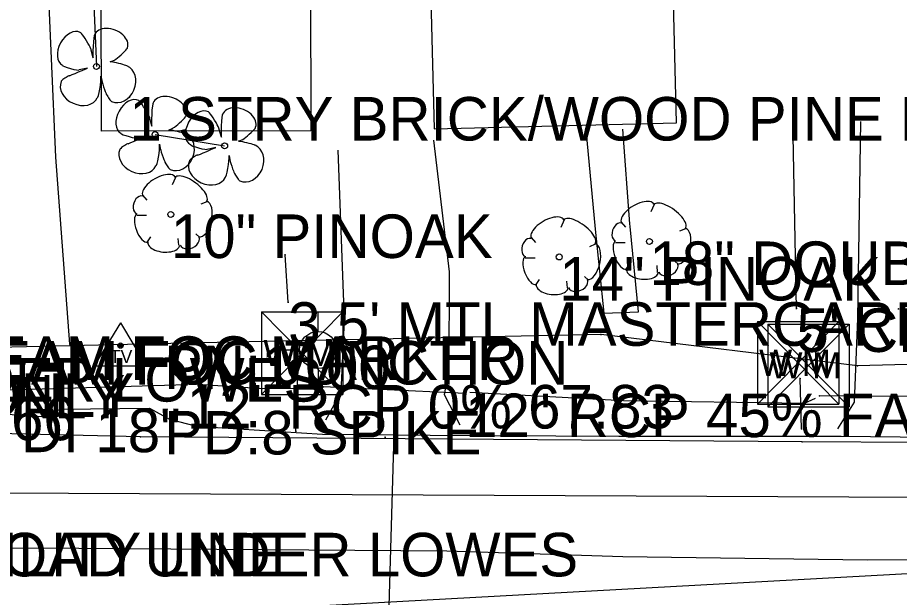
# Model space of a CAD drawing. Extents: x 1304270 to 1306561, y 1876019 to 1876752.
# Drawn here: x 1305034.9 to 1305136, y 1876403.7 to 1876470.3 of the extents above; entities that cross this region are included whole.
import ezdxf

# ---------------------------------------------------------------- set-up
doc = ezdxf.new("R2010")
doc.units = 0
for name, color, linetype in [('Default', 7, 'Continuous'), ('S_BUILDING', 7, 'Continuous'), ('S_BUILDING_ANNOT', 7, 'Continuous'), ('S_DITCHLINE', 7, 'Continuous'), ('S_DRG_PT_SYM', 7, 'Continuous'), ('S_DRIVEWAY', 7, 'Continuous'), ('S_EDGE_PAVEMENT', 7, 'Continuous'), ('S_ELECTRIC_UTILITIES_ANNOT', 7, 'Continuous'), ('S_FENCE', 7, 'Continuous'), ('S_FENCE_ANNOT', 7, 'Continuous'), ('S_FIBER_OPTIC_CABLE', 7, 'Continuous'), ('S_MSC_PT_SYM', 7, 'Continuous'), ('S_PAVEMENT_CROWN', 7, 'Continuous'), ('S_SANITARY_SEWER', 7, 'Continuous'), ('S_SECONDARY_CTL', 7, 'Continuous'), ('S_SECONDARY_CTL_ANNOT', 7, 'Continuous'), ('S_SIDE_DRAIN', 7, 'Continuous'), ('S_SIDE_DRAIN_ANNOT', 7, 'Continuous'), ('S_SIDEWALK', 7, 'Continuous'), ('S_SIGN', 7, 'Continuous'), ('S_SIGN_ANNOT', 7, 'Continuous'), ('S_STORM_SEWER_ANNOT', 7, 'Continuous'), ('S_STR_PT_SYM', 7, 'Continuous'), ('S_SURVEY_TEXT_ANNOT', 7, 'Continuous'), ('S_TELEPHONE_UTILITIES_ANNOT', 7, 'Continuous'), ('S_TREE', 7, 'Continuous'), ('S_TREE_ANNOT', 7, 'Continuous'), ('S_UTILITY_POLE', 7, 'Continuous'), ('S_UTILITY_POLE_ANNOT', 7, 'Continuous'), ('S_UTL_PT_SYM', 7, 'Continuous'), ('S_WATER_UTILITIES', 7, 'Continuous')]:
    doc.layers.add(name, color=color, linetype=linetype)

msp = doc.modelspace()

# ---------------------------------------------------------------- linework, layer by layer
at = {"layer": 'Default'}
msp.add_line((1304873.94, 1876392.06), (1305473.53, 1876424.94), dxfattribs=at)
at = {"layer": 'S_BUILDING'}
for points in [[(1305044.48, 1876457.27), (1305044.38, 1876507.06), (1305040.43, 1876507.05), (1305040.41, 1876515.92), (1305043.37, 1876515.92), (1305043.27, 1876566.2), (1305064.01, 1876566.25), (1305064.12, 1876507.43), (1305068.4, 1876507.44), (1305068.5, 1876457.32)], [(1305110.49, 1876458.23), (1305109.44, 1876499.79), (1305081.6, 1876499.08), (1305082.65, 1876457.52)]]:
    msp.add_lwpolyline(points, close=True, dxfattribs=at)
at = {"layer": 'S_DITCHLINE'}
for points in [[(1305054.97, 1876428.26), (1305062.99, 1876427.7), (1305069.3, 1876427.77)], [(1305086.77, 1876427.29), (1305104.4, 1876426.33), (1305125.17, 1876426.04), (1305126.42, 1876426.61)]]:
    msp.add_lwpolyline(points, dxfattribs=at)
at = {"layer": 'S_DRG_PT_SYM'}
for points in [[(1305054.28, 1876428.12), (1305054.28, 1876428.17), (1305054.28, 1876428.12), (1305054.23, 1876428.12), (1305054.28, 1876428.12), (1305054.28, 1876428.07), (1305054.28, 1876428.12), (1305054.33, 1876428.12)], [(1305069.97, 1876427.91), (1305069.97, 1876427.96), (1305069.97, 1876427.91), (1305069.92, 1876427.91), (1305069.97, 1876427.91), (1305069.97, 1876427.86), (1305069.97, 1876427.91), (1305070.02, 1876427.91)], [(1305086.22, 1876427.13), (1305086.22, 1876427.18), (1305086.22, 1876427.13), (1305086.17, 1876427.13), (1305086.22, 1876427.13), (1305086.22, 1876427.08), (1305086.22, 1876427.13), (1305086.27, 1876427.13)], [(1305126.89, 1876426.87), (1305126.89, 1876426.92), (1305126.89, 1876426.87), (1305126.84, 1876426.87), (1305126.89, 1876426.87), (1305126.89, 1876426.82), (1305126.89, 1876426.87), (1305126.94, 1876426.87)]]:
    msp.add_lwpolyline(points, dxfattribs=at)
at = {"layer": 'S_DRIVEWAY'}
for points in [[(1305045.18, 1876426.29), (1305040.87, 1876432.82), (1305039.24, 1876454.28), (1305038.25, 1876476.97), (1305037.26, 1876499.66)], [(1305129, 1876423.09), (1305130.9, 1876426.13), (1305131.29, 1876435.75), (1305131.62, 1876458.39)], [(1305082.58, 1876456.23), (1305084.4, 1876441.12), (1305084.34, 1876429.84), (1305083.83, 1876427.04), (1305085.6, 1876423.53)], [(1305070.25, 1876424.11), (1305071.99, 1876427.31), (1305072.37, 1876435.56), (1305071.64, 1876455.07)]]:
    msp.add_lwpolyline(points, dxfattribs=at)
at = {"layer": 'S_EDGE_PAVEMENT'}
msp.add_lwpolyline([(1305027.35, 1876425.19), (1305037.63, 1876424.5), (1305039.84, 1876425.35), (1305050, 1876425.46), (1305052.3, 1876424.19), (1305055.39, 1876423.4), (1305069.86, 1876422.47), (1305082.2, 1876422.36), (1305103.86, 1876422.24), (1305116.61, 1876422.24), (1305129.36, 1876422.24), (1305153.05, 1876421.96)], dxfattribs=at)
at = {"layer": 'S_FENCE'}
msp.add_line((1305124.23, 1876436.91), (1305123.87, 1876456.74), dxfattribs=at)
msp.add_lwpolyline([(1305124.23, 1876436.91), (1305123.87, 1876456.74)], dxfattribs=at)
msp.add_lwpolyline([(1305124.23, 1876436.91), (1305123.87, 1876456.74)], dxfattribs=at)
at = {"layer": 'S_FIBER_OPTIC_CABLE'}
for p, q in [((1305101.81, 1876433.92), (1305054.08, 1876432.91)), ((1305131.24, 1876430.32), (1305101.81, 1876433.92)), ((1305054.08, 1876432.91), (1305001.63, 1876431.73)), ((1305161.12, 1876431.11), (1305131.24, 1876430.32))]:
    msp.add_line(p, q, dxfattribs=at)
at = {"layer": 'S_MSC_PT_SYM'}
for points in [[(1305123.87, 1876456.74), (1305123.87, 1876456.79), (1305123.87, 1876456.74), (1305123.82, 1876456.74), (1305123.87, 1876456.74), (1305123.87, 1876456.69), (1305123.87, 1876456.74), (1305123.92, 1876456.74)], [(1305065.55, 1876443.07), (1305065.55, 1876443.12), (1305065.55, 1876443.07), (1305065.5, 1876443.07), (1305065.55, 1876443.07), (1305065.55, 1876443.02), (1305065.55, 1876443.07), (1305065.6, 1876443.07)], [(1305065.91, 1876437.62), (1305065.91, 1876437.67), (1305065.91, 1876437.62), (1305065.86, 1876437.62), (1305065.91, 1876437.62), (1305065.91, 1876437.57), (1305065.91, 1876437.62), (1305065.96, 1876437.62)], [(1305124.23, 1876436.91), (1305124.23, 1876436.96), (1305124.23, 1876436.91), (1305124.18, 1876436.91), (1305124.23, 1876436.91), (1305124.23, 1876436.86), (1305124.23, 1876436.91), (1305124.28, 1876436.91)], [(1305135.95, 1876436.85), (1305135.95, 1876436.9), (1305135.95, 1876436.85), (1305135.9, 1876436.85), (1305135.95, 1876436.85), (1305135.95, 1876436.8), (1305135.95, 1876436.85), (1305136, 1876436.85)]]:
    msp.add_lwpolyline(points, dxfattribs=at)
at = {"layer": 'S_PAVEMENT_CROWN'}
msp.add_lwpolyline([(1304919.66, 1876411.01), (1304932.57, 1876410.53), (1304945.47, 1876410.05), (1304958.3, 1876409.86), (1304971.12, 1876409.67), (1304984.31, 1876409.56), (1304997.49, 1876409.46), (1305019.68, 1876409.41), (1305041.87, 1876409.36), (1305062.99, 1876409.23), (1305084.1, 1876409.09), (1305104.33, 1876408.42), (1305118.33, 1876408.24), (1305132.34, 1876408.05), (1305154.42, 1876408.07)], dxfattribs=at)
at = {"layer": 'S_SANITARY_SEWER'}
msp.add_line((1304983.66, 1876415.96), (1305346.23, 1876414.24), dxfattribs=at)
at = {"layer": 'S_SECONDARY_CTL'}
for p, q in [((1305046.67, 1876435.25), (1305043.66, 1876430.3)), ((1305046.67, 1876435.25), (1305049.62, 1876430.3)), ((1305043.66, 1876430.3), (1305049.62, 1876430.3))]:
    msp.add_line(p, q, dxfattribs=at)
for radius in [0.311, 0.183, 0.103]:
    msp.add_circle((1305046.67, 1876432.64), radius, dxfattribs=at)
at = {"layer": 'S_SIDE_DRAIN'}
for p, q in [((1305054.28, 1876428.12), (1304986.49, 1876426.16)), ((1305086.22, 1876427.13), (1305069.97, 1876427.91)), ((1305143.1, 1876426.78), (1305126.89, 1876426.87))]:
    msp.add_line(p, q, dxfattribs=at)
at = {"layer": 'S_SIDEWALK'}
msp.add_lwpolyline([(1305100.06, 1876457.44), (1305101.13, 1876446.01), (1305102.12, 1876436.36), (1305106.12, 1876436.52), (1305105.17, 1876446.32), (1305105.1, 1876446.62), (1305104.32, 1876457.49)], dxfattribs=at)
at = {"layer": 'S_SIGN'}
msp.add_line((1305065.91, 1876437.62), (1305065.55, 1876443.07), dxfattribs=at)
at = {"layer": 'S_STR_PT_SYM'}
msp.add_lwpolyline([(1305047.7, 1876461.19), (1305047.7, 1876461.24), (1305047.7, 1876461.19), (1305047.65, 1876461.19), (1305047.7, 1876461.19), (1305047.7, 1876461.14), (1305047.7, 1876461.19), (1305047.75, 1876461.19)], dxfattribs=at)
at = {"layer": 'S_TREE'}
for p, q in [((1305042.39, 1876501.21), (1305043.91, 1876464.7)), ((1305043.55, 1876465.68), (1305043.3, 1876466.57)), ((1305045.49, 1876465.22), (1305045.87, 1876465.38)), ((1305042.9, 1876464.51), (1305041.92, 1876464.3)), ((1305044.43, 1876463.58), (1305044.51, 1876463.14)), ((1305050.27, 1876457.86), (1305050.03, 1876458.76)), ((1305052.22, 1876457.4), (1305052.6, 1876457.56)), ((1305058.25, 1876456.56), (1305058.01, 1876457.45)), ((1305049.62, 1876456.7), (1305048.65, 1876456.48)), ((1305050.64, 1876456.88), (1305058.62, 1876455.58)), ((1305060.2, 1876456.1), (1305060.58, 1876456.26)), ((1305051.15, 1876455.77), (1305051.23, 1876455.33)), ((1305057.6, 1876455.4), (1305056.63, 1876455.18)), ((1305059.14, 1876454.47), (1305059.22, 1876454.03)), ((1305052.99, 1876451.95), (1305052.61, 1876451.1)), ((1305049.2, 1876449.93), (1305049.7, 1876449.35)), ((1305056.56, 1876449.16), (1305055.9, 1876448.89)), ((1305107.93, 1876448.84), (1305107.54, 1876447.99)), ((1305048.54, 1876447.61), (1305049.66, 1876447.61)), ((1305097.57, 1876447.07), (1305097.19, 1876446.21)), ((1305104.13, 1876446.83), (1305104.63, 1876446.25)), ((1305111.49, 1876446.05), (1305110.83, 1876445.78)), ((1305049.7, 1876444.43), (1305050.16, 1876445.13)), ((1305053.38, 1876444.16), (1305053.3, 1876444.94)), ((1305055.78, 1876445.05), (1305055.32, 1876445.48)), ((1305093.78, 1876445.05), (1305094.28, 1876444.47)), ((1305101.14, 1876444.28), (1305100.48, 1876444)), ((1305103.47, 1876444.5), (1305104.59, 1876444.5)), ((1305093.12, 1876442.73), (1305094.24, 1876442.73)), ((1305104.63, 1876441.32), (1305105.1, 1876442.02)), ((1305108.31, 1876441.05), (1305108.24, 1876441.83)), ((1305110.72, 1876441.94), (1305110.25, 1876442.37)), ((1305094.28, 1876439.55), (1305094.74, 1876440.25)), ((1305097.96, 1876439.28), (1305097.88, 1876440.05)), ((1305100.36, 1876440.17), (1305099.9, 1876440.59))]:
    msp.add_line(p, q, dxfattribs=at)
for centre in [(1305043.91, 1876464.7), (1305050.64, 1876456.88), (1305058.62, 1876455.58), (1305052.44, 1876447.7), (1305107.37, 1876444.6), (1305097.02, 1876442.82)]:
    msp.add_circle(centre, 0.341, dxfattribs=at)
for centre, major_axis, ratio, start_param, end_param in [((1305045.57, 1876467.59), (1.89, -0.74), 0.673998, 0, 3.141593), ((1305041.03, 1876466.72), (-1.03, -1.88), 0.662338, 3.141593, 6.283185), ((1305042.68, 1876467.59), (0.62, -1.01), 0.083512, 0, 3.141593), ((1305043.61, 1876467), (-0.07, -1.33), 0.068203, 3.141593, 6.283185), ((1305046.67, 1876466.11), (-0.798, -0.73), 0.092159, 0, 3.141593), ((1305046.45, 1876464.99), (0.96, -0.23), 0.056001, 0, 3.141593), ((1305040.96, 1876464.57), (0.964, -0.267), 0.113563, 3.141593, 6.283185), ((1305041.86, 1876464.07), (1.04, 0.44), 0.002756, 3.141593, 6.283185), ((1305046.53, 1876462.71), (0.88, 2.05), 0.81717, 3.141593, 6.283185), ((1305041.94, 1876462.04), (2.07, -0.93), 0.760068, 3.141593, 6.283185), ((1305040.34, 1876463.3), (0.477, 0.328), 0.136309, 0, 3.141593), ((1305044.19, 1876462.42), (0.19, 1.31), 0.114148, 3.141593, 5.822668), ((1305044.76, 1876462.37), (0.254, -0.771), 0.051603, 3.141593, 6.283185), ((1305045.34, 1876461.14), (-0.321, 0.467), 0.094289, 0, 3.141593), ((1305047.75, 1876458.9), (-1.03, -1.88), 0.662338, 3.141593, 6.283185), ((1305052.3, 1876459.77), (1.89, -0.74), 0.673998, 0, 3.141593), ((1305049.4, 1876459.77), (0.62, -1.01), 0.083512, 0, 3.141593), ((1305050.34, 1876459.19), (-0.07, -1.33), 0.068203, 3.141593, 6.283185), ((1305060.28, 1876458.47), (1.89, -0.74), 0.673998, 0, 3.141593), ((1305053.39, 1876458.3), (-0.798, -0.73), 0.092159, 0, 3.141593), ((1305055.73, 1876457.6), (-1.03, -1.88), 0.662338, 3.141593, 6.283185), ((1305057.39, 1876458.47), (0.62, -1.01), 0.083512, 0, 3.141593), ((1305058.32, 1876457.89), (-0.07, -1.33), 0.068203, 3.141593, 6.283185), ((1305047.68, 1876456.75), (0.964, -0.267), 0.113563, 3.141593, 6.283185), ((1305053.18, 1876457.17), (0.96, -0.23), 0.056001, 0, 3.141593), ((1305053.26, 1876454.9), (0.88, 2.05), 0.81717, 3.141593, 6.283185), ((1305061.38, 1876456.99), (-0.798, -0.73), 0.092159, 0, 3.141593), ((1305048.58, 1876456.26), (1.04, 0.44), 0.002756, 3.141593, 6.283185), ((1305061.16, 1876455.87), (0.96, -0.23), 0.056001, 0, 3.141593), ((1305048.66, 1876454.22), (2.07, -0.93), 0.760068, 3.141593, 6.283185), ((1305047.07, 1876455.48), (0.477, 0.328), 0.136309, 0, 3.141593), ((1305050.92, 1876454.6), (0.19, 1.31), 0.114148, 3.141593, 5.822668), ((1305051.49, 1876454.56), (0.254, -0.771), 0.051603, 3.141593, 6.283185), ((1305055.67, 1876455.45), (0.964, -0.267), 0.113563, 3.141593, 6.283185), ((1305056.57, 1876454.95), (1.04, 0.44), 0.002756, 3.141593, 6.283185), ((1305061.24, 1876453.6), (0.88, 2.05), 0.81717, 3.141593, 6.283185), ((1305055.05, 1876454.18), (0.477, 0.328), 0.136309, 0, 3.141593), ((1305058.9, 1876453.3), (0.19, 1.31), 0.114148, 3.141593, 5.822668), ((1305059.47, 1876453.26), (0.254, -0.771), 0.051603, 3.141593, 6.283185), ((1305052.06, 1876453.32), (-0.321, 0.467), 0.094289, 0, 3.141593), ((1305056.64, 1876452.92), (2.07, -0.93), 0.760068, 3.141593, 6.283185), ((1305051.1, 1876450.91), (1.86, 1.08), 0.471018, 0, 3.141593), ((1305054.75, 1876450.58), (-1.81, 1.36), 0.405113, 3.141593, 6.283186), ((1305060.05, 1876452.02), (-0.321, 0.467), 0.094289, 0, 3.141593), ((1305048.86, 1876448.79), (0.31, 1.03), 0.646762, 0, 3.141593), ((1305056.11, 1876447.17), (0.46, 2.04), 0.482994, 3.141593, 6.283185), ((1305106.03, 1876447.8), (1.86, 1.08), 0.471018, 0, 3.141593), ((1305109.69, 1876447.47), (-1.81, 1.36), 0.405113, 3.141593, 6.283186), ((1305049.17, 1876446.14), (-0.61, 1.6), 0.420543, 6.283185, 9.424777), ((1305095.68, 1876446.02), (1.86, 1.08), 0.471018, 0, 3.141593), ((1305099.33, 1876445.7), (-1.81, 1.36), 0.405113, 3.141593, 6.283186), ((1305103.8, 1876445.68), (0.31, 1.03), 0.646762, 0, 3.141593), ((1305111.04, 1876444.07), (0.46, 2.04), 0.482994, 3.141593, 6.283185), ((1305054.59, 1876444.65), (1.09, 0.46), 0.711534, 3.141592, 6.283185), ((1305093.44, 1876443.91), (0.31, 1.03), 0.646762, 0, 3.141593), ((1305051.63, 1876444.36), (-1.83, 0.19), 0.529943, 0, 3.141593), ((1305100.69, 1876442.29), (0.46, 2.04), 0.482994, 3.141593, 6.283185), ((1305104.1, 1876443.03), (-0.61, 1.6), 0.420543, 6.283185, 9.424777), ((1305093.75, 1876441.26), (-0.61, 1.6), 0.420543, 6.283185, 9.424777), ((1305109.52, 1876441.55), (1.09, 0.46), 0.711534, 3.141592, 6.283185), ((1305106.56, 1876441.25), (-1.83, 0.19), 0.529943, 0, 3.141593), ((1305099.17, 1876439.77), (1.09, 0.46), 0.711534, 3.141592, 6.283185), ((1305096.21, 1876439.48), (-1.83, 0.19), 0.529943, 0, 3.141593)]:
    msp.add_ellipse(centre, major_axis=major_axis, ratio=ratio, start_param=start_param, end_param=end_param, dxfattribs=at)
at = {"layer": 'S_UTILITY_POLE'}
for p, q in [((1305069.34, 1876434.24), (1305069.34, 1876436.49)), ((1305067.24, 1876432.11), (1305064.92, 1876432.11)), ((1305069.41, 1876427.69), (1305069.41, 1876430.02))]:
    msp.add_line(p, q, dxfattribs=at)
msp.add_circle((1305069.34, 1876432.13), 2.13, dxfattribs=at)
at = {"layer": 'S_UTL_PT_SYM'}
for points in [[(1305101.81, 1876433.92), (1305101.81, 1876433.97), (1305101.81, 1876433.92), (1305101.76, 1876433.92), (1305101.81, 1876433.92), (1305101.81, 1876433.87), (1305101.81, 1876433.92), (1305101.86, 1876433.92)], [(1305054.08, 1876432.91), (1305054.08, 1876432.96), (1305054.08, 1876432.91), (1305054.03, 1876432.91), (1305054.08, 1876432.91), (1305054.08, 1876432.86), (1305054.08, 1876432.91), (1305054.13, 1876432.91)], [(1305067.01, 1876429.81), (1305067.01, 1876429.86), (1305067.01, 1876429.81), (1305066.96, 1876429.81), (1305067.01, 1876429.81), (1305067.01, 1876429.76), (1305067.01, 1876429.81), (1305067.06, 1876429.81)], [(1305131.24, 1876430.32), (1305131.24, 1876430.37), (1305131.24, 1876430.32), (1305131.19, 1876430.32), (1305131.24, 1876430.32), (1305131.24, 1876430.27), (1305131.24, 1876430.32), (1305131.29, 1876430.32)], [(1305124.65, 1876428.86), (1305124.65, 1876428.91), (1305124.65, 1876428.86), (1305124.6, 1876428.86), (1305124.65, 1876428.86), (1305124.65, 1876428.81), (1305124.65, 1876428.86), (1305124.7, 1876428.86)], [(1305066.8, 1876422.81), (1305066.8, 1876422.86), (1305066.8, 1876422.81), (1305066.75, 1876422.81), (1305066.8, 1876422.81), (1305066.8, 1876422.76), (1305066.8, 1876422.81), (1305066.85, 1876422.81)], [(1305124.83, 1876423.08), (1305124.83, 1876423.13), (1305124.83, 1876423.08), (1305124.78, 1876423.08), (1305124.83, 1876423.08), (1305124.83, 1876423.03), (1305124.83, 1876423.08), (1305124.88, 1876423.08)], [(1305048.97, 1876422.17), (1305048.97, 1876422.22), (1305048.97, 1876422.17), (1305048.92, 1876422.17), (1305048.97, 1876422.17), (1305048.97, 1876422.12), (1305048.97, 1876422.17), (1305049.02, 1876422.17)], [(1305077.06, 1876422.11), (1305077.06, 1876422.16), (1305077.06, 1876422.11), (1305077.01, 1876422.11), (1305077.06, 1876422.11), (1305077.06, 1876422.06), (1305077.06, 1876422.11), (1305077.11, 1876422.11)], [(1305124.9, 1876421.59), (1305124.9, 1876421.64), (1305124.9, 1876421.59), (1305124.85, 1876421.59), (1305124.9, 1876421.59), (1305124.9, 1876421.54), (1305124.9, 1876421.59), (1305124.95, 1876421.59)], [(1305078.04, 1876421.15), (1305078.04, 1876421.2), (1305078.04, 1876421.15), (1305077.99, 1876421.15), (1305078.04, 1876421.15), (1305078.04, 1876421.1), (1305078.04, 1876421.15), (1305078.09, 1876421.15)]]:
    msp.add_lwpolyline(points, dxfattribs=at)
at = {"layer": 'S_WATER_UTILITIES'}
for p, q in [((1305062.86, 1876436.51), (1305072.2, 1876436.51)), ((1305062.86, 1876436.51), (1305062.86, 1876427.02)), ((1305062.86, 1876436.51), (1305072.2, 1876427.02)), ((1305072.2, 1876436.51), (1305062.86, 1876427.02)), ((1305072.2, 1876436.51), (1305072.2, 1876427.02)), ((1305119.75, 1876435.39), (1305129.09, 1876435.39)), ((1305119.75, 1876435.39), (1305119.75, 1876425.9)), ((1305119.75, 1876435.39), (1305129.09, 1876425.9)), ((1305129.09, 1876435.39), (1305119.75, 1876425.9)), ((1305120.95, 1876435.11), (1305130.29, 1876435.11)), ((1305120.95, 1876435.11), (1305120.95, 1876425.61)), ((1305120.95, 1876435.11), (1305130.29, 1876425.61)), ((1305130.29, 1876435.11), (1305120.95, 1876425.61)), ((1305129.09, 1876435.39), (1305129.09, 1876425.9)), ((1305130.29, 1876435.11), (1305130.29, 1876425.61)), ((1305066.8, 1876422.81), (1305067.01, 1876429.81)), ((1305124.83, 1876423.08), (1305124.65, 1876428.86)), ((1305062.86, 1876427.02), (1305072.2, 1876427.02)), ((1305119.75, 1876425.9), (1305129.09, 1876425.9)), ((1305120.95, 1876425.61), (1305130.29, 1876425.61)), ((1305048.97, 1876422.17), (1304991.8, 1876423.43)), ((1305124.9, 1876421.59), (1305048.97, 1876422.17)), ((1305219.44, 1876420.93), (1305124.9, 1876421.59)), ((1305077.27, 1876394.82), (1305078.04, 1876421.15))]:
    msp.add_line(p, q, dxfattribs=at)

# ---------------------------------------------------------------- texts
at = {"layer": 'S_BUILDING_ANNOT'}
msp.add_text('1 STRY BRICK/WOOD PINE BLUFF SW', height=5, dxfattribs=at).set_placement((1305047.7, 1876456.19))
at = {"layer": 'S_ELECTRIC_UTILITIES_ANNOT'}
for p in [(1304964.71, 1876426.21), (1304994.06, 1876406.14)]:
    msp.add_text('POINT ON ROAD UNDER LOWES', height=5, dxfattribs=at).set_placement(p)
at = {"layer": 'S_FENCE_ANNOT'}
msp.add_text("5' CHAINLINK/MTL POST FAIR", height=5, dxfattribs=at).set_placement((1305124.23, 1876431.91))
at = {"layer": 'S_SECONDARY_CTL'}
msp.add_text('TV', height=1.5, rotation=360, dxfattribs=at).set_placement((1305045.46, 1876430.63))
at = {"layer": 'S_SECONDARY_CTL_ANNOT'}
for s, p in [('PN:1100', (1305051.67, 1876427.64)), ('PD:8 SPIKE', (1305051.67, 1876420.14))]:
    msp.add_text(s, height=5, dxfattribs=at).set_placement(p)
at = {"layer": 'S_SIDE_DRAIN_ANNOT'}
for s, p in [('12" RCP 0% 67.83', (1305054.28, 1876423.12)), ('12" RCP 0% 12.66', (1304985.65, 1876421.77)), ('12" RCP 45% FAIR 16.26', (1305086.22, 1876422.13)), ('12" 18" RCP 0% DI 18"', (1304984.41, 1876420.4))]:
    msp.add_text(s, height=5, dxfattribs=at).set_placement(p)
at = {"layer": 'S_SIGN_ANNOT'}
msp.add_text("3.5' MTL MASTERCARD/VISA/DISCOVER", height=5, dxfattribs=at).set_placement((1305065.91, 1876432.62))
at = {"layer": 'S_STORM_SEWER_ANNOT'}
for p in [(1304962.76, 1876424.27), (1304963.77, 1876424.46)]:
    msp.add_text('18" RCP DIRECTION ONLY', height=5, dxfattribs=at).set_placement(p)
at = {"layer": 'S_SURVEY_TEXT_ANNOT'}
for p in [(1304964.71, 1876426.21), (1304994.06, 1876406.14)]:
    msp.add_text('LOWEST UTILITY LINE', height=5, dxfattribs=at).set_placement(p)
at = {"layer": 'S_TELEPHONE_UTILITIES_ANNOT'}
msp.add_text('WINDSTREAM FOC JUNCTION', height=5, dxfattribs=at).set_placement((1305000.75, 1876428.17))
at = {"layer": 'S_TREE_ANNOT'}
for s, p in [('10" PINOAK', (1305052.44, 1876442.7)), ('18" DOUBLE PINOAK', (1305107.37, 1876439.6)), ('14" PINOAK', (1305097.02, 1876437.82))]:
    msp.add_text(s, height=5, dxfattribs=at).set_placement(p)
at = {"layer": 'S_UTILITY_POLE_ANNOT'}
msp.add_text('WINDSTREAM FOC MARKER', height=5, dxfattribs=at).set_placement((1305000.26, 1876428.7))
at = {"layer": 'S_WATER_UTILITIES'}
for p in [(1305063.06, 1876430.28), (1305119.96, 1876429.16), (1305121.15, 1876428.87)]:
    msp.add_text('W M', height=3, rotation=360, dxfattribs=at).set_placement(p)

doc.saveas('drawing.dxf')
